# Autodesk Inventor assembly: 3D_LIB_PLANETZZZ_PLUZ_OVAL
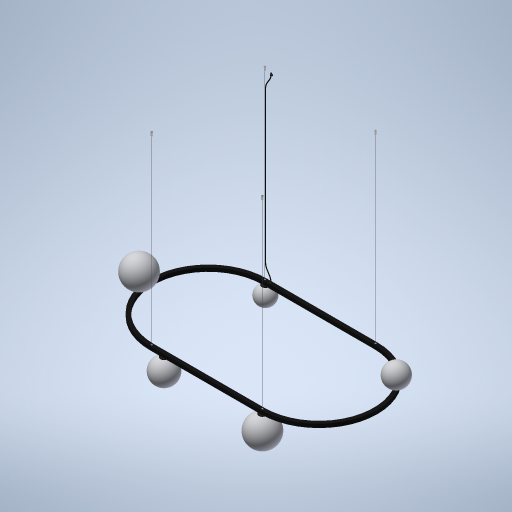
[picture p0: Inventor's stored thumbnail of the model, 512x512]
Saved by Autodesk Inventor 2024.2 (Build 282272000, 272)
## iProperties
Created: 2023-11
Part Number: 3D_LIB_PLANETZZZ_PLUZ_OVAL
Document SubType Name: Assembly
Designer: Manuel
Project: 453 - PLANETZZZ
Description: PLANETZZZ Oval 950x1850 - Assy
Manager: Filip
Company: DARK
Author: Manuel
Revision Number: v0
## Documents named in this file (14)
- C:\Users\Stage\Desktop\Stage Karsten\armatures\453 - PLANETZZZ\453_KARSTEN\3D_LIB_PLANETZZZ_PLUZ_OVAL.iam
- C:\Users\Stage\Desktop\TUUR\2D en 3D\PLANETZZZ PLUZ\PLANETZZZ PLUZ\400-032.ipt
- C:\Users\Stage\Desktop\TUUR\2D en 3D\PLANETZZZ PLUZ\PLANETZZZ PLUZ\190-1000-000001.ipt
- C:\Users\Stage\Desktop\TUUR\2D en 3D\PLANETZZZ PLUZ\PLANETZZZ PLUZ\190-1000-000008.ipt
- C:\Users\Stage\Desktop\TUUR\2D en 3D\PLANETZZZ PLUZ\PLANETZZZ PLUZ\190-1000-000009.ipt
- C:\Users\Stage\Desktop\TUUR\2D en 3D\PLANETZZZ PLUZ\PLANETZZZ PLUZ\190-2012-001500.ipt
- C:\Users\Stage\Desktop\TUUR\2D en 3D\PLANETZZZ PLUZ\PLANETZZZ PLUZ\453-100.iam
- C:\Users\Stage\Desktop\TUUR\2D en 3D\PLANETZZZ PLUZ\PLANETZZZ PLUZ\PLANETZZZ - Moon dia 150 Assy.iam
- C:\Users\Stage\Desktop\TUUR\2D en 3D\PLANETZZZ PLUZ\PLANETZZZ PLUZ\PLANETZZZ - Moon dia 180 Assy.iam
- C:\Users\Stage\Desktop\TUUR\2D en 3D\PLANETZZZ PLUZ\PLANETZZZ PLUZ\PLANETZZZ - Moon dia 200 Assy.iam
- C:\Users\Stage\Desktop\TUUR\2D en 3D\PLANETZZZ PLUZ\PLANETZZZ PLUZ\PLANETZZZ - Moon dia 240 Assy.iam
- C:\Users\Stage\Desktop\TUUR\2D en 3D\PLANETZZZ PLUZ\PLANETZZZ PLUZ\120-4000-000014.ipt
- N:\PROJECTS\225 - PLAFONDPOTJES\225-740.iam
- C:\Users\Stage\Desktop\TUUR\2D en 3D\PLANETZZZ PLUZ\PLANETZZZ PLUZ\Alimentation 5P - 1472.ipt
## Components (31 placed, 13 different names)
1. 400-032:1
2. 190-1000-000001:1 — Flush:7, Mate:1, Mate:5
3. Suspension part fixture M10x1 - ø2mm:1 — Flush:4, Mate:6, Mate:7, Mate:11, Mate:15
4. 190-1000-000009:1 — Flush:1, Mate:1, Mate:2, Mate:11
5. 190-1000-000001:2 — Flush:7, Flush:8, Mate:2
6. Suspension part fixture M10x1 - ø2mm:2 — Flush:4, Flush:5, Mate:8, Mate:13, Mate:17
7. 190-1000-000009:2 — Flush:1, Flush:2, Mate:3, Mate:12, Flush:22
8. 190-1000-000001:3 — Flush:8, Flush:9, Mate:3
9. Suspension part fixture M10x1 - ø2mm:3 — Flush:5, Flush:6, Mate:9, Mate:12, Mate:16
10. 190-1000-000009:3 — Flush:2, Flush:3, Mate:4, Mate:13, Flush:10
11. 190-1000-000001:4 — Flush:9, Mate:4
12. Suspension part fixture M10x1 - ø2mm:4 — Flush:6, Mate:10, Mate:14, Mate:18
13. 190-1000-000009:4 — Flush:3, Mate:5, Mate:14
14. 190-2012-001500:1 — Flush:11, Flush:14, Mate:15
15. 190-2012-001500:2 — Flush:11, Flush:12, Mate:16, Mate:45
16. 190-2012-001500:3 — Flush:12, Flush:13, Mate:17
17. 190-2012-001500:4 — Flush:13, Mate:18
18. 453-100:1 [sub-assembly] — Flush:15, Mate:23, Mate:24, Mate:32
19. 453-100:2 [sub-assembly] — Flush:15, Mate:19, Mate:21, Mate:22, Mate:31, Mate:33
20. 453-100:3 [sub-assembly] — Flush:17, Flush:18, Mate:20, Mate:25, Mate:26, Mate:34, Mate:36
21. 453-100:4 [sub-assembly] — Flush:17, Mate:29, Mate:30, Mate:37
22. 453-100:5 [sub-assembly] — Flush:18, Mate:27, Mate:28, Mate:35
23. PLANETZZZ - Moon dia 150 Assy:1 [sub-assembly] — Flush:20, Mate:37
24. PLANETZZZ - Moon dia 180 Assy:1 [sub-assembly] — Flush:19, Mate:31, Mate:32
25. PLANETZZZ - Moon dia 200 Assy:1 [sub-assembly] — Flush:20, Flush:21, Mate:36
26. PLANETZZZ - Moon dia 240 Assy:1 [sub-assembly] — Flush:21, Mate:34, Mate:35
27. PLANETZZZ - Moon dia 240 Assy:2 [sub-assembly] — Flush:19, Mate:33
28. 120-4000-000014:1 — Mate:38, Mate:39, Angle:1, Mate:40, Mate:44
29. 225-740:1 [sub-assembly] — Flush:22, Mate:40, Angle:2, Mate:41, Mate:42, Angle:3
30. 120-4000-000014:2 — Mate:41, Mate:42, Angle:3
31. Alimentation 5P - 1472:1 — Mate:43, Mate:44, Mate:45
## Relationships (69: Mate 45, Flush 21, Angle 3)
- Flush:1: 190-1000-000009:1 ↔ 190-1000-000009:2
- Flush:2: 190-1000-000009:2 ↔ 190-1000-000009:3
- Flush:3: 190-1000-000009:3 ↔ 190-1000-000009:4
- Flush:4: Suspension part fixture M10x1 - ø2mm:1 ↔ Suspension part fixture M10x1 - ø2mm:2
- Flush:5: Suspension part fixture M10x1 - ø2mm:2 ↔ Suspension part fixture M10x1 - ø2mm:3
- Flush:6: Suspension part fixture M10x1 - ø2mm:3 ↔ Suspension part fixture M10x1 - ø2mm:4
- Flush:7: 190-1000-000001:1 ↔ 190-1000-000001:2
- Flush:8: 190-1000-000001:2 ↔ 190-1000-000001:3
- Flush:9: 190-1000-000001:3 ↔ 190-1000-000001:4
- Mate:1: 190-1000-000001:1 ↔ 190-1000-000009:1
- Mate:2: 190-1000-000009:1 ↔ 190-1000-000001:2
- Mate:3: 190-1000-000009:2 ↔ 190-1000-000001:3
- Mate:4: 190-1000-000009:3 ↔ 190-1000-000001:4
- Mate:5: 190-1000-000001:1 ↔ 190-1000-000009:4
- Mate:6: Suspension part fixture M10x1 - ø2mm:1
- Mate:7: Suspension part fixture M10x1 - ø2mm:1
- Mate:8: Suspension part fixture M10x1 - ø2mm:2
- Mate:9: Suspension part fixture M10x1 - ø2mm:3
- Mate:10: Suspension part fixture M10x1 - ø2mm:4
- Mate:11: Suspension part fixture M10x1 - ø2mm:1 ↔ 190-1000-000009:1
- Mate:12: 190-1000-000009:2 ↔ Suspension part fixture M10x1 - ø2mm:3
- Mate:13: Suspension part fixture M10x1 - ø2mm:2 ↔ 190-1000-000009:3
- Mate:14: Suspension part fixture M10x1 - ø2mm:4 ↔ 190-1000-000009:4
- Flush:10: 190-1000-000009:3
- Flush:11: 190-2012-001500:1 ↔ 190-2012-001500:2
- Flush:12: 190-2012-001500:2 ↔ 190-2012-001500:3
- Flush:13: 190-2012-001500:3 ↔ 190-2012-001500:4
- Flush:14: 190-2012-001500:1
- Mate:15: Suspension part fixture M10x1 - ø2mm:1 ↔ 190-2012-001500:1
- Mate:16: Suspension part fixture M10x1 - ø2mm:3 ↔ 190-2012-001500:2
- Mate:17: Suspension part fixture M10x1 - ø2mm:2 ↔ 190-2012-001500:3
- Mate:18: Suspension part fixture M10x1 - ø2mm:4 ↔ 190-2012-001500:4
- Flush:15: 453-100:1 ↔ 453-100:2
- Flush:17: 453-100:3 ↔ 453-100:4
- Flush:18: 453-100:3 ↔ 453-100:5
- Mate:19: 453-100:2
- Mate:20: 453-100:3
- Mate:21: 453-100:2
- Mate:22: 453-100:2
- Mate:23: 453-100:1
- Mate:24: 453-100:1
- Mate:25: 453-100:3
- Mate:26: 453-100:3
- Mate:27: 453-100:5
- Mate:28: 453-100:5
- Mate:29: 453-100:4
- Mate:30: 453-100:4
- Flush:19: PLANETZZZ - Moon dia 180 Assy:1 ↔ PLANETZZZ - Moon dia 240 Assy:2
- Mate:31: 453-100:2 ↔ PLANETZZZ - Moon dia 180 Assy:1
- Mate:32: 453-100:1 ↔ PLANETZZZ - Moon dia 180 Assy:1
- Mate:33: 453-100:2 ↔ PLANETZZZ - Moon dia 240 Assy:2
- Flush:20: PLANETZZZ - Moon dia 150 Assy:1 ↔ PLANETZZZ - Moon dia 200 Assy:1
- Flush:21: PLANETZZZ - Moon dia 200 Assy:1 ↔ PLANETZZZ - Moon dia 240 Assy:1
- Mate:34: 453-100:3 ↔ PLANETZZZ - Moon dia 240 Assy:1
- Mate:35: 453-100:5 ↔ PLANETZZZ - Moon dia 240 Assy:1
- Mate:36: 453-100:3 ↔ PLANETZZZ - Moon dia 200 Assy:1
- Mate:37: 453-100:4 ↔ PLANETZZZ - Moon dia 150 Assy:1
- Mate:38: 120-4000-000014:1
- Mate:39: 120-4000-000014:1
- Angle:1: 120-4000-000014:1
- Flush:22: 190-1000-000009:2 ↔ 225-740:1
- Mate:40: 120-4000-000014:1 ↔ 225-740:1
- Angle:2: 225-740:1
- Mate:41: 225-740:1 ↔ 120-4000-000014:2
- Mate:42: 225-740:1 ↔ 120-4000-000014:2
- Angle:3: 225-740:1 ↔ 120-4000-000014:2
- Mate:43: Alimentation 5P - 1472:1
- Mate:44: 120-4000-000014:1 ↔ Alimentation 5P - 1472:1
- Mate:45: 190-2012-001500:2 ↔ Alimentation 5P - 1472:1
